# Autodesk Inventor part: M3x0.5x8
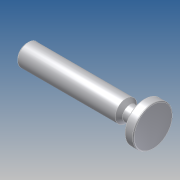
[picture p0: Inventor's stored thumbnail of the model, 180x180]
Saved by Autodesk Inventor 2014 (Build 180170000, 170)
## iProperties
Company: 한국ATC센터
Created: 2009-02
Part Number: M3x0.5x8
Document SubType Name: Modeling
Designer: KYOUNG IL JANG
Density: 7.86 g/cm^3
Mass: 68.0563 g
Surface Area: 34.7349 cm^2
Volume: 8.65856 cm^3
Material: 강, 연강
Vendor: CBT Solutions
Appearance: 강철
Author: KYOUNG IL JANG
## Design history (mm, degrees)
sketch "스케치1"
  geometry: L1 (-35, 0)-(35, 0); L2 (35, 0)-(35, 11); L3 (35, 11)-(30, 11); L4 (30, 11)-(30, 4); L5 (30, 4)-(22, 4); L6 (22, 4)-(20, 6); L7 (20, 6)-(-35, 6); L8 (-35, 6)-(-35, 0); 1 further point
  constraints: 16 end point, 4 parallel, 2 midpoint, 2 perpendicular, 1 horizontal
  dimensions: "d0" = 70 distance of L1.start L1.end; "d1" = 12 diameter of L7 L1; "d2" = 22 diameter of L3 L1; "d3" = 5 distance of L2.end L3.end; "d4" = 8 diameter of L5 L1; "d5" = 135 deg angle of L6 L5; "d6" = 15 distance from line of L2 L6.end
revolve "회전1" sketch "스케치1" stored, may be unused: angle "d7" = 90 deg
chamfer "모따기1" distance "d8" = 1; stored, may be unused: second distance "d9" = 2, angle "d10" = 45 deg
fillet "모깎기1" dims "d11" = 0.5
node "솔리드1"
